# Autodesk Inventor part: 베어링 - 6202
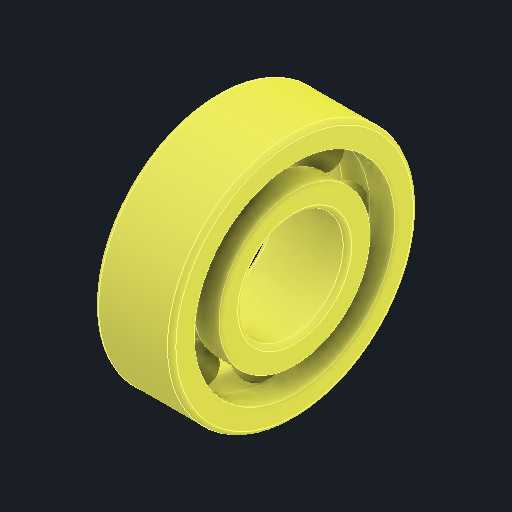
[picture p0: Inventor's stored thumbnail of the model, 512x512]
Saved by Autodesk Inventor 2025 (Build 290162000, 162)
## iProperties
Created: 2025-08
Part Number: 베어링 - 6202
Material: 강, 연강
Description: 깊은 그루브 볼 베어링
Document SubType Name: Modeling
Designer: infra023
Density: 7.86 g/cm^3
Appearance: 기본값
Author: jhkim
Sending System: Autodesk Inventor 2026
Preprocessor: ST-DEVELOPER v20.1
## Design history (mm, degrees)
feature "Solid1"
feature "Solid1:1"
feature "Solid1:2"
feature "Solid1:3"
feature "Solid1:4"
feature "Solid1:5"
feature "Solid1:6"
feature "Solid1:7"
feature "Solid1:8"
feature "Solid1:9"
node "솔리드1"
node "솔리드2"
node "솔리드3"
node "솔리드4"
node "솔리드5"
node "솔리드6"
node "솔리드7"
node "솔리드8"
node "솔리드9"
node "솔리드10"
